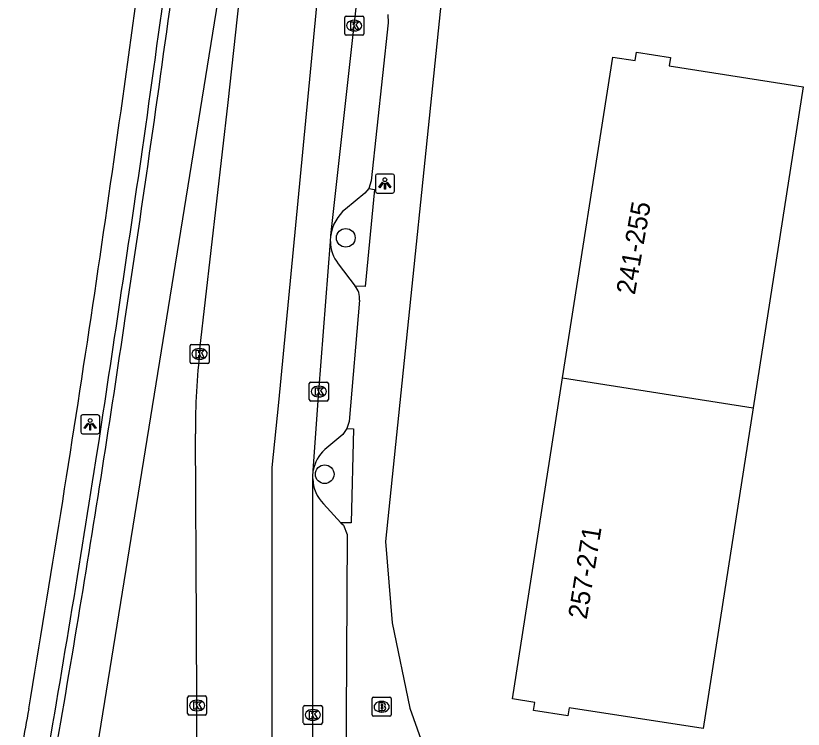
# Model space of a CAD drawing. Extents: x 163010 to 163853, y 382793 to 383982.
# Drawn here: x 163173.41 to 163214.78, y 383071.57 to 383109.07 of the extents above; entities that cross this region are included whole.
import ezdxf

# ---------------------------------------------------------------- set-up
doc = ezdxf.new("R2010")
doc.units = 0
for name, color, linetype in [('IMGEO_Boom', 7, 'Continuous'), ('IMGEO_Brandkraan', 7, 'Continuous'), ('IMGEO_Fietspad_gesloten', 7, 'Continuous'), ('IMGEO_Haag', 7, 'Continuous'), ('IMGEO_Kolk', 7, 'Continuous'), ('IMGEO_Lichtpunt', 7, 'Continuous'), ('IMGEO_Muur', 7, 'Continuous'), ('IMGEO_Pand', 7, 'Continuous'), ('IMGEO_Pand_nummerreeks', 7, 'Continuous'), ('IMGEO_Parkeervlak_open', 7, 'Continuous'), ('IMGEO_Rijbaan_lokaal_gesloten', 7, 'Continuous'), ('IMGEO_Rijbaan_regionaal_gesloten', 7, 'Continuous'), ('IMGEO_Voetpad_open', 7, 'Continuous')]:
    doc.layers.add(name, color=color, linetype=linetype)

msp = doc.modelspace()

# ---------------------------------------------------------------- linework, layer by layer
at = {"layer": 'IMGEO_Boom'}
for centre in [(163190.745, 383097.398), (163189.639, 383084.975)]:
    msp.add_circle(centre, 0.489, dxfattribs=at)
at = {"layer": 'IMGEO_Brandkraan'}
for p, q in [((163192.129, 383072.331), (163192.129, 383073.183)), ((163192.204, 383073.257), (163193.056, 383073.257)), ((163193.13, 383073.183), (163193.13, 383072.331)), ((163192.617, 383073.037), (163192.642, 383073.037)), ((163192.64, 383072.477), (163192.615, 383072.477)), ((163193.056, 383072.257), (163192.204, 383072.257))]:
    msp.add_line(p, q, dxfattribs=at)
for points in [[(163192.129, 383072.331), (163192.129, 383073.183)], [(163192.204, 383073.257), (163193.056, 383073.257)], [(163193.13, 383073.183), (163193.13, 383072.331)], [(163192.477, 383072.957), (163192.477, 383072.557), (163192.69, 383072.557)], [(163192.708, 383072.957), (163192.477, 383072.957)], [(163192.656, 383072.876), (163192.602, 383072.876), (163192.602, 383072.8)], [(163192.602, 383072.8), (163192.655, 383072.8)], [(163192.664, 383072.724), (163192.602, 383072.724), (163192.602, 383072.643)], [(163192.602, 383072.643), (163192.664, 383072.643)], [(163193.056, 383072.257), (163192.204, 383072.257)]]:
    msp.add_lwpolyline(points, dxfattribs=at)
for centre, radius, start, end in [((163192.206, 383073.181), 0.0765, 91.552, 178.448), ((163192.206, 383073.181), 0.0765, 91.552, 178.448), ((163193.054, 383073.181), 0.0765, 1.552, 88.448), ((163193.054, 383073.181), 0.0765, 1.552, 88.448), ((163192.657, 383072.838), 0.0379, 267.8285, 90.9355), ((163192.712, 383072.812), 0.145, 59.4692, 91.5367), ((163192.737, 383072.859), 0.0922, 285.5137, 58.1501), ((163192.742, 383072.667), 0.105, 301.3115, 78.989), ((163192.206, 383072.333), 0.0765, 181.552, 268.448), ((163192.206, 383072.333), 0.0765, 181.552, 268.448), ((163192.665, 383072.683), 0.0404, 269.8759, 90.5077), ((163192.696, 383072.808), 0.251, 268.6676, 293.5347), ((163193.054, 383072.333), 0.0765, 271.552, 358.448), ((163193.054, 383072.333), 0.0765, 271.552, 358.448)]:
    msp.add_arc(centre, radius, start, end, dxfattribs=at)
for centre, major_axis, ratio, start_param, end_param in [((163192.616, 383072.757), (-0.387, 0.002), 0.722429, 4.712389, 7.853982), ((163192.641, 383072.757), (-0.39, 0.002), 0.717154, 1.570796, 4.712389)]:
    msp.add_ellipse(centre, major_axis=major_axis, ratio=ratio, start_param=start_param, end_param=end_param, dxfattribs=at)
at = {"layer": 'IMGEO_Fietspad_gesloten'}
for points in [[(163189.965, 383097.523), (163191.189, 383108.548), (163191.556, 383111.789)], [(163189.036, 383085.163), (163189.329, 383089.321), (163189.94, 383097.197)], [(163189.94, 383097.197), (163189.965, 383097.523)], [(163189.013, 383084.73), (163189.013, 383084.841), (163189.036, 383085.163)], [(163189.011, 383062.854), (163189.015, 383072.329), (163189.013, 383084.73)]]:
    msp.add_lwpolyline(points, dxfattribs=at)
at = {"layer": 'IMGEO_Haag'}
msp.add_lwpolyline([(163176.129, 383060.902), (163186.656, 383126.053)], dxfattribs=at)
at = {"layer": 'IMGEO_Kolk'}
for p, q in [((163190.69, 383108.122), (163190.69, 383108.974)), ((163190.765, 383109.048), (163191.617, 383109.048)), ((163191.178, 383108.828), (163191.203, 383108.828)), ((163191.691, 383108.974), (163191.691, 383108.122)), ((163191.617, 383108.048), (163190.765, 383108.048)), ((163191.201, 383108.268), (163191.176, 383108.268)), ((163182.642, 383091.798), (163183.494, 383091.798)), ((163182.567, 383090.872), (163182.567, 383091.724)), ((163183.055, 383091.578), (163183.08, 383091.578)), ((163183.568, 383091.724), (163183.568, 383090.872)), ((163183.078, 383091.018), (163183.053, 383091.018)), ((163183.494, 383090.798), (163182.642, 383090.798)), ((163188.83, 383088.895), (163188.83, 383089.747)), ((163188.905, 383089.821), (163189.757, 383089.821)), ((163189.831, 383089.747), (163189.831, 383088.895)), ((163189.318, 383089.601), (163189.343, 383089.601)), ((163189.341, 383089.041), (163189.316, 383089.041)), ((163189.757, 383088.821), (163188.905, 383088.821)), ((163182.436, 383072.396), (163182.436, 383073.248)), ((163182.511, 383073.322), (163183.363, 383073.322)), ((163183.437, 383073.248), (163183.437, 383072.396)), ((163182.924, 383073.102), (163182.949, 383073.102)), ((163188.516, 383071.903), (163188.516, 383072.755)), ((163188.591, 383072.829), (163189.443, 383072.829)), ((163189.517, 383072.755), (163189.517, 383071.903)), ((163182.947, 383072.542), (163182.922, 383072.542)), ((163189.004, 383072.609), (163189.029, 383072.609)), ((163183.363, 383072.322), (163182.511, 383072.322)), ((163189.027, 383072.049), (163189.002, 383072.049)), ((163189.443, 383071.829), (163188.591, 383071.829))]:
    msp.add_line(p, q, dxfattribs=at)
for points in [[(163190.69, 383108.122), (163190.69, 383108.974)], [(163190.765, 383109.048), (163191.617, 383109.048)], [(163191.011, 383108.748), (163191.134, 383108.748), (163191.134, 383108.597), (163191.264, 383108.748), (163191.428, 383108.748), (163191.282, 383108.597), (163191.435, 383108.348), (163191.283, 383108.348), (163191.198, 383108.512), (163191.134, 383108.445), (163191.134, 383108.348), (163191.011, 383108.348), (163191.011, 383108.748)], [(163191.691, 383108.974), (163191.691, 383108.122)], [(163191.617, 383108.048), (163190.765, 383108.048)], [(163182.642, 383091.798), (163183.494, 383091.798)], [(163182.567, 383090.872), (163182.567, 383091.724)], [(163182.888, 383091.498), (163183.011, 383091.498), (163183.011, 383091.347), (163183.141, 383091.498), (163183.305, 383091.498), (163183.159, 383091.347), (163183.312, 383091.098), (163183.16, 383091.098), (163183.075, 383091.262), (163183.011, 383091.195), (163183.011, 383091.098), (163182.888, 383091.098), (163182.888, 383091.498)], [(163183.568, 383091.724), (163183.568, 383090.872)], [(163183.494, 383090.798), (163182.642, 383090.798)], [(163188.83, 383088.895), (163188.83, 383089.747)], [(163188.905, 383089.821), (163189.757, 383089.821)], [(163189.831, 383089.747), (163189.831, 383088.895)], [(163189.151, 383089.521), (163189.274, 383089.521), (163189.274, 383089.37), (163189.404, 383089.521), (163189.568, 383089.521), (163189.422, 383089.37), (163189.575, 383089.121), (163189.423, 383089.121), (163189.338, 383089.285), (163189.274, 383089.218), (163189.274, 383089.121), (163189.151, 383089.121), (163189.151, 383089.521)], [(163189.757, 383088.821), (163188.905, 383088.821)], [(163182.436, 383072.396), (163182.436, 383073.248)], [(163182.511, 383073.322), (163183.363, 383073.322)], [(163183.437, 383073.248), (163183.437, 383072.396)], [(163182.757, 383073.022), (163182.88, 383073.022), (163182.88, 383072.871), (163183.01, 383073.022), (163183.174, 383073.022), (163183.028, 383072.871), (163183.181, 383072.622), (163183.029, 383072.622), (163182.944, 383072.786), (163182.88, 383072.719), (163182.88, 383072.622), (163182.757, 383072.622), (163182.757, 383073.022)], [(163188.516, 383071.903), (163188.516, 383072.755)], [(163188.591, 383072.829), (163189.443, 383072.829)], [(163189.517, 383072.755), (163189.517, 383071.903)], [(163188.837, 383072.529), (163188.96, 383072.529), (163188.96, 383072.378), (163189.09, 383072.529), (163189.254, 383072.529), (163189.108, 383072.378), (163189.261, 383072.129), (163189.109, 383072.129), (163189.024, 383072.293), (163188.96, 383072.226), (163188.96, 383072.129), (163188.837, 383072.129), (163188.837, 383072.529)], [(163183.363, 383072.322), (163182.511, 383072.322)], [(163189.443, 383071.829), (163188.591, 383071.829)]]:
    msp.add_lwpolyline(points, dxfattribs=at)
for centre, start, end in [((163190.767, 383108.972), 91.552, 178.448), ((163190.767, 383108.972), 91.552, 178.448), ((163191.615, 383108.972), 1.552, 88.448), ((163191.615, 383108.972), 1.552, 88.448), ((163190.767, 383108.124), 181.552, 268.448), ((163190.767, 383108.124), 181.552, 268.448), ((163191.615, 383108.124), 271.552, 358.448), ((163191.615, 383108.124), 271.552, 358.448), ((163182.644, 383091.722), 91.552, 178.448), ((163182.644, 383091.722), 91.552, 178.448), ((163183.492, 383091.722), 1.552, 88.448), ((163183.492, 383091.722), 1.552, 88.448), ((163182.644, 383090.874), 181.552, 268.448), ((163182.644, 383090.874), 181.552, 268.448), ((163183.492, 383090.874), 271.552, 358.448), ((163183.492, 383090.874), 271.552, 358.448), ((163188.907, 383089.745), 91.552, 178.448), ((163188.907, 383089.745), 91.552, 178.448), ((163189.755, 383089.745), 1.552, 88.448), ((163189.755, 383089.745), 1.552, 88.448), ((163188.907, 383088.897), 181.552, 268.448), ((163188.907, 383088.897), 181.552, 268.448), ((163189.755, 383088.897), 271.552, 358.448), ((163189.755, 383088.897), 271.552, 358.448), ((163182.513, 383073.246), 91.552, 178.448), ((163182.513, 383073.246), 91.552, 178.448), ((163183.361, 383073.246), 1.552, 88.448), ((163183.361, 383073.246), 1.552, 88.448), ((163188.593, 383072.753), 91.552, 178.448), ((163188.593, 383072.753), 91.552, 178.448), ((163189.441, 383072.753), 1.552, 88.448), ((163189.441, 383072.753), 1.552, 88.448), ((163182.513, 383072.398), 181.552, 268.448), ((163182.513, 383072.398), 181.552, 268.448), ((163183.361, 383072.398), 271.552, 358.448), ((163183.361, 383072.398), 271.552, 358.448), ((163188.593, 383071.905), 181.552, 268.448), ((163188.593, 383071.905), 181.552, 268.448), ((163189.441, 383071.905), 271.552, 358.448), ((163189.441, 383071.905), 271.552, 358.448)]:
    msp.add_arc(centre, 0.0765, start, end, dxfattribs=at)
for centre, major_axis, ratio, start_param, end_param in [((163191.177, 383108.548), (-0.387, 0.002), 0.722429, 4.712389, 7.853982), ((163191.202, 383108.548), (-0.39, 0.002), 0.717154, 1.570796, 4.712389), ((163183.054, 383091.298), (-0.387, 0.002), 0.722429, 4.712389, 7.853982), ((163183.079, 383091.298), (-0.39, 0.002), 0.717154, 1.570796, 4.712389), ((163189.317, 383089.321), (-0.387, 0.002), 0.722429, 4.712389, 7.853982), ((163189.342, 383089.321), (-0.39, 0.002), 0.717154, 1.570796, 4.712389), ((163182.923, 383072.822), (-0.387, 0.002), 0.722429, 4.712389, 7.853982), ((163182.948, 383072.822), (-0.39, 0.002), 0.717154, 1.570796, 4.712389), ((163189.003, 383072.329), (-0.387, 0.002), 0.722429, 4.712389, 7.853982), ((163189.028, 383072.329), (-0.39, 0.002), 0.717154, 1.570796, 4.712389)]:
    msp.add_ellipse(centre, major_axis=major_axis, ratio=ratio, start_param=start_param, end_param=end_param, dxfattribs=at)
at = {"layer": 'IMGEO_Lichtpunt'}
for p, q in [((163192.303, 383100.654), (163192.303, 383099.847)), ((163192.303, 383100.654), (163192.303, 383099.847)), ((163193.205, 383100.749), (163192.397, 383100.749)), ((163193.205, 383100.749), (163192.397, 383100.749)), ((163193.299, 383099.847), (163193.299, 383100.654)), ((163193.299, 383099.847), (163193.299, 383100.654)), ((163192.397, 383099.753), (163193.205, 383099.753)), ((163192.397, 383099.753), (163193.205, 383099.753)), ((163177.724, 383088.097), (163176.916, 383088.097)), ((163177.724, 383088.097), (163176.916, 383088.097)), ((163176.822, 383088.002), (163176.822, 383087.195)), ((163176.822, 383088.002), (163176.822, 383087.195)), ((163177.818, 383087.195), (163177.818, 383088.002)), ((163177.818, 383087.195), (163177.818, 383088.002)), ((163176.916, 383087.101), (163177.724, 383087.101)), ((163176.916, 383087.101), (163177.724, 383087.101))]:
    msp.add_line(p, q, dxfattribs=at)
for points in [[(163192.677, 383100.318), (163192.716, 383100.29), (163192.528, 383100.028), (163192.49, 383100.055), (163192.677, 383100.318)], [(163192.779, 383100.27), (163192.826, 383100.27), (163192.826, 383099.948), (163192.779, 383099.948), (163192.779, 383100.27)], [(163192.889, 383100.29), (163192.927, 383100.317), (163193.114, 383100.055), (163193.075, 383100.027), (163192.889, 383100.29)], [(163177.196, 383087.666), (163177.235, 383087.638), (163177.047, 383087.376), (163177.009, 383087.403), (163177.196, 383087.666)], [(163177.408, 383087.638), (163177.446, 383087.665), (163177.633, 383087.403), (163177.594, 383087.375), (163177.408, 383087.638)], [(163177.298, 383087.618), (163177.345, 383087.618), (163177.345, 383087.296), (163177.298, 383087.296), (163177.298, 383087.618)]]:
    msp.add_lwpolyline(points, dxfattribs=at)
for centre in [(163192.802, 383100.452), (163177.321, 383087.8)]:
    msp.add_circle(centre, 0.0994, dxfattribs=at)
for centre, start, end in [((163192.397, 383100.654), 90, 180), ((163192.397, 383100.654), 90, 180), ((163193.205, 383100.654), 0, 90), ((163193.205, 383100.654), 0, 90), ((163192.397, 383099.847), 180, 270), ((163192.397, 383099.847), 180, 270), ((163193.205, 383099.847), 270, 0), ((163193.205, 383099.847), 270, 360), ((163176.916, 383088.002), 90, 180), ((163176.916, 383088.002), 90, 180), ((163177.724, 383088.002), 0, 90), ((163177.724, 383088.002), 0, 90), ((163176.916, 383087.195), 180, 270), ((163176.916, 383087.195), 180, 270), ((163177.724, 383087.195), 270, 0), ((163177.724, 383087.195), 270, 360)]:
    msp.add_arc(centre, 0.0946, start, end, dxfattribs=at)
at = {"layer": 'IMGEO_Muur'}
for centre, radius, start, end in [((161264.689, 383371.891), 1934.295, 351.980351, 352.559763), ((162206.008, 383241.675), 984.418, 351.322355, 352.413116), ((159935.901, 383577.787), 3278.865, 351.377852, 351.65707), ((162362.518, 383212.608), 825.33, 350.573511, 351.677848), ((162185.474, 383241.118), 1004.252, 350.10546, 351.127623), ((161778.46, 383310.27), 1417.496, 349.892236, 350.545839)]:
    msp.add_arc(centre, radius, start, end, dxfattribs=at)
at = {"layer": 'IMGEO_Pand'}
for points in [[(163202.135, 383090.034), (163204.767, 383106.897), (163205.944, 383106.713), (163206.012, 383107.149), (163207.8, 383106.87), (163207.732, 383106.434), (163214.776, 383105.335), (163212.144, 383088.472)], [(163212.144, 383088.472), (163209.513, 383071.609), (163202.479, 383072.706), (163202.412, 383072.274), (163200.614, 383072.554), (163200.681, 383072.987), (163199.504, 383073.171), (163202.135, 383090.034)], [(163202.135, 383090.034), (163212.144, 383088.472)]]:
    msp.add_lwpolyline(points, dxfattribs=at)
at = {"layer": 'IMGEO_Parkeervlak_open'}
for points in [[(163191.955, 383099.985), (163191.739, 383099.741), (163190.731, 383098.911)], [(163190.354, 383096.038), (163191.232, 383094.862)], [(163190.804, 383087.37), (163190.589, 383087.068), (163189.649, 383086.27)], [(163189.574, 383083.423), (163190.492, 383082.414)]]:
    msp.add_lwpolyline(points, dxfattribs=at)
for centre, radius, start, end in [((163192.089, 383097.256), 2.14, 129.3688, 172.8449), ((163191.814, 383097.213), 1.874, 180.4907, 218.8232), ((163190.868, 383084.872), 1.855, 131.0858, 170.9633), ((163190.946, 383084.786), 1.934, 181.6539, 224.8067)]:
    msp.add_arc(centre, radius, start, end, dxfattribs=at)
at = {"layer": 'IMGEO_Rijbaan_lokaal_gesloten'}
for points in [[(163195.025, 383213.387), (163195.659, 383206.771), (163194.656, 383191.361), (163192.885, 383158.536), (163191.232, 383130.905), (163188.871, 383106.11), (163187.218, 383088.753), (163186.864, 383085.328), (163186.864, 383060.867)], [(163183.088, 383091.543), (163184.56, 383104.506), (163185.35, 383111.765), (163185.753, 383116.011), (163186.175, 383120.606), (163186.656, 383126.053)], [(163182.979, 383062.325), (163182.964, 383064.559), (163182.912, 383077.047), (163182.846, 383087.101)]]:
    msp.add_lwpolyline(points, dxfattribs=at)
msp.add_arc((163220.105, 383087.299), 37.26, 173.4592, 180.304, dxfattribs=at)
at = {"layer": 'IMGEO_Rijbaan_regionaal_gesloten'}
for centre, radius, start, end in [((161782.082, 383300.585), 1410.613, 351.546131, 352.385741), ((161962.25, 383276.27), 1228.83, 350.461459, 351.43253), ((164337.739, 382861.43), 1182.66, 169.712494, 169.898904)]:
    msp.add_arc(centre, radius, start, end, dxfattribs=at)
at = {"layer": 'IMGEO_Voetpad_open'}
for points in [[(163196.282, 383114.913), (163192.827, 383081.438), (163193.185, 383077.161), (163194.113, 383072.68), (163195.651, 383068.334)], [(163192.955, 383109.136), (163192.98, 383108.697), (163192.087, 383100.384), (163191.955, 383099.985)], [(163191.955, 383099.985), (163192.253, 383099.936), (163191.758, 383094.835), (163191.232, 383094.862)], [(163191.465, 383094.123), (163190.927, 383087.746), (163190.804, 383087.37)], [(163190.804, 383087.37), (163191.147, 383087.355), (163191.036, 383082.428), (163190.492, 383082.414)], [(163190.492, 383082.414), (163190.623, 383082.296), (163190.81, 383081.806), (163190.724, 383065.784)]]:
    msp.add_lwpolyline(points, dxfattribs=at)
msp.add_arc((163190.481, 383094.219), 0.989, 354.429, 40.5702, dxfattribs=at)

# ---------------------------------------------------------------- texts
at = {"layer": 'IMGEO_Pand_nummerreeks'}
for s, rotation, p in [('241-255', 80.0738, (163205.928, 383094.37)), ('257-271', 80.7701, (163203.401, 383077.317))]:
    msp.add_text(s, height=1, rotation=rotation, dxfattribs=at).set_placement(p)

doc.saveas('drawing.dxf')
